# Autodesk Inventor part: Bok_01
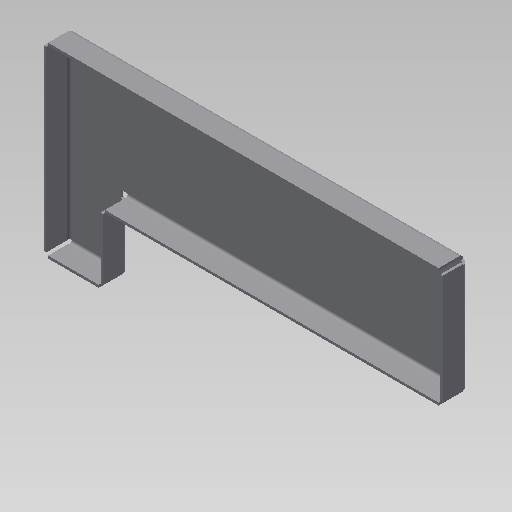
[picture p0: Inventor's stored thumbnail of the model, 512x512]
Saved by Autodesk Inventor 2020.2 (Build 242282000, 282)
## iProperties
Created: 2014-09
Part Number: Bok_01
Material: Ogólny
Document SubType Name: Konstrukcja blachowa
Designer: F.Stasiak
Density: 1 g/cm^3
Sheet Metal Rule: Domyślny_mm
Appearance: Domyślna
Catalog Web Link: www.expertbooks.pl
Manager: www.cadconsulting.pl
Company: Fabian Stasiak CAD Consulting
Author: F.Stasiak
Subject: Zbiór ćwiczeń. Autodesk Inventor 2020. Kurs Professional
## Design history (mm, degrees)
node "Powierzchnia1"
  sketch "Szkic1"
    geometry: L1 (-200, -40)-(-200, 0); L2 (-200, 0)-(0, 0); L3 (0, 0)-(0, 70); L4 (0, 70)-(-235, 70); L5 (-235, 70)-(-235, -40); L6 (-235, -40)-(-200, -40); 1 further point
    constraints: 12 end point, 5 perpendicular, 1 coincident, 1 vertical
    dimensions: "d0" = 200 distance of L1.end L2.end; "d1" = 40 distance of L1.start L1.end; "d2" = 110 distance of L4.end L5.end; "d3" = 35 distance of L5.end L1.start
node "Kołnierz1"
node "Bryła1"
feature "Płyta1" dims "d15" = 1.5 (= Grubość)
sketch "Szkic2"
  geometry: L1 (0, 15)-(-110, 15); L2 (-110, 15)-(-110, 0); 1 other entity
  constraints: 4 end point, 4 other
feature "Płyta2" dims "d5" = 1.5 (= SzerokośćGięciaPodcięcia), "d6" = 0.75 (= GłębokośćGięciaPodcięcia), "d7" = 3 (= MinimalnaPozostałość), "d8" = 1.5 (= PromieńGięcia), "d9" = 15, "d10" = 90 deg, "d11" = 1.5 (= PromieńGięcia), "d12" = 6 (= RozmiarPodcięciaNarożnika), "d13" = 1.5 (= Wielk_odstępu), "d14" = 1.5 (= Rozmiar_promienia_Jacobiego), "d15" = 1.5 (= Grubość), "OdstępPołączenia" = 0.01
feature "Gięcie1" dims "d5" = 1.5 (= SzerokośćGięciaPodcięcia), "d6" = 0.75 (= GłębokośćGięciaPodcięcia), "d7" = 3 (= MinimalnaPozostałość), "d8" = 1.5 (= PromieńGięcia), "d9" = 15, "d10" = 90 deg, "d11" = 1.5 (= PromieńGięcia), "d15" = 1.5 (= Grubość), "OdstępPołączenia" = 0.01
feature "Narożnik1" dims "d9" = 15, "d10" = 90 deg, "d12" = 6 (= RozmiarPodcięciaNarożnika), "d13" = 1.5 (= Wielk_odstępu), "d14" = 1.5 (= Rozmiar_promienia_Jacobiego)
other parameters: "Grubość" = 1.5 (derived), "WspółczynnikK" = 4.4, "PromieńGięcia" = 1.5 (= Grubość), "SzerokośćGięciaPodcięcia" = 1.5 (= Grubość), "GłębokośćGięciaPodcięcia" = 0.75 (= 0.5 x Grubość), "RozmiarPodcięciaNarożnika" = 6 (= 4 x Grubość), "MinimalnaPozostałość" = 3 (= 2 x Grubość), "PromieńPrzejścia" = 1.5 (= PromieńGięcia), "Rozmiar_promienia_Jacobiego" = 1.5 (= PromieńGięcia), "Wielk_odstępu" = 1.5 (= Grubość), "d4" = 1.5 (= PromieńGięcia)
